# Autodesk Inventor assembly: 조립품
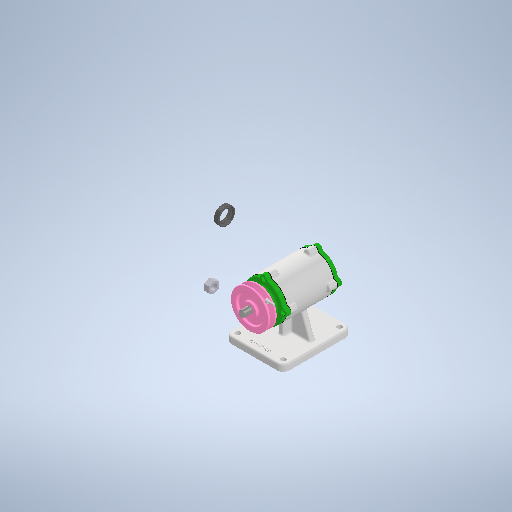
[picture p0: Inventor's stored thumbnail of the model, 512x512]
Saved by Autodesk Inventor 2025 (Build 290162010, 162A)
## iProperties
Created: 2024-08
Part Number: 조립품
Document SubType Name: Assembly
Designer: 학생
Author: 학생
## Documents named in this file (12)
- C:\Users\학생\Desktop\740807V1012\740807V1012\조립품.iam
- C:\Users\학생\Desktop\740807V1012\740807V1012\본체.ipt
- C:\Users\학생\Desktop\740807V1012\740807V1012\V-벨트풀리\V-벨트풀리.ipt
- C:\Users\학생\Desktop\740807V1012\740807V1012\개스킷\개스킷.ipt
- C:\Users\학생\Desktop\740807V1012\740807V1012\너트 M12 x 1.25\너트 M12 x 1.25.ipt
- C:\Users\학생\Desktop\740807V1012\740807V1012\뒤커버\뒤커버.ipt
- C:\Users\학생\Desktop\740807V1012\740807V1012\베어링 6204\베어링 6204.ipt
- C:\Users\학생\Desktop\740807V1012\740807V1012\볼트 M4 x 12\볼트 M4 x 12.ipt
- C:\Users\학생\Desktop\740807V1012\740807V1012\앞커버\앞커버.ipt
- C:\Users\학생\Desktop\740807V1012\740807V1012\오일실\오일실.ipt
- C:\Users\학생\Desktop\740807V1012\740807V1012\축\축.ipt
- C:\Users\학생\Desktop\740807V1012\740807V1012\키 4 x 4\키 4 x 4.ipt
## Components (3 placed, 2 different names)
1. V-벨트풀리:1 — 각도:2
2. 개스킷:1
3. 개스킷:2
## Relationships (1: Angle 1)
- 각도:2 [Angle]: V-벨트풀리:1
